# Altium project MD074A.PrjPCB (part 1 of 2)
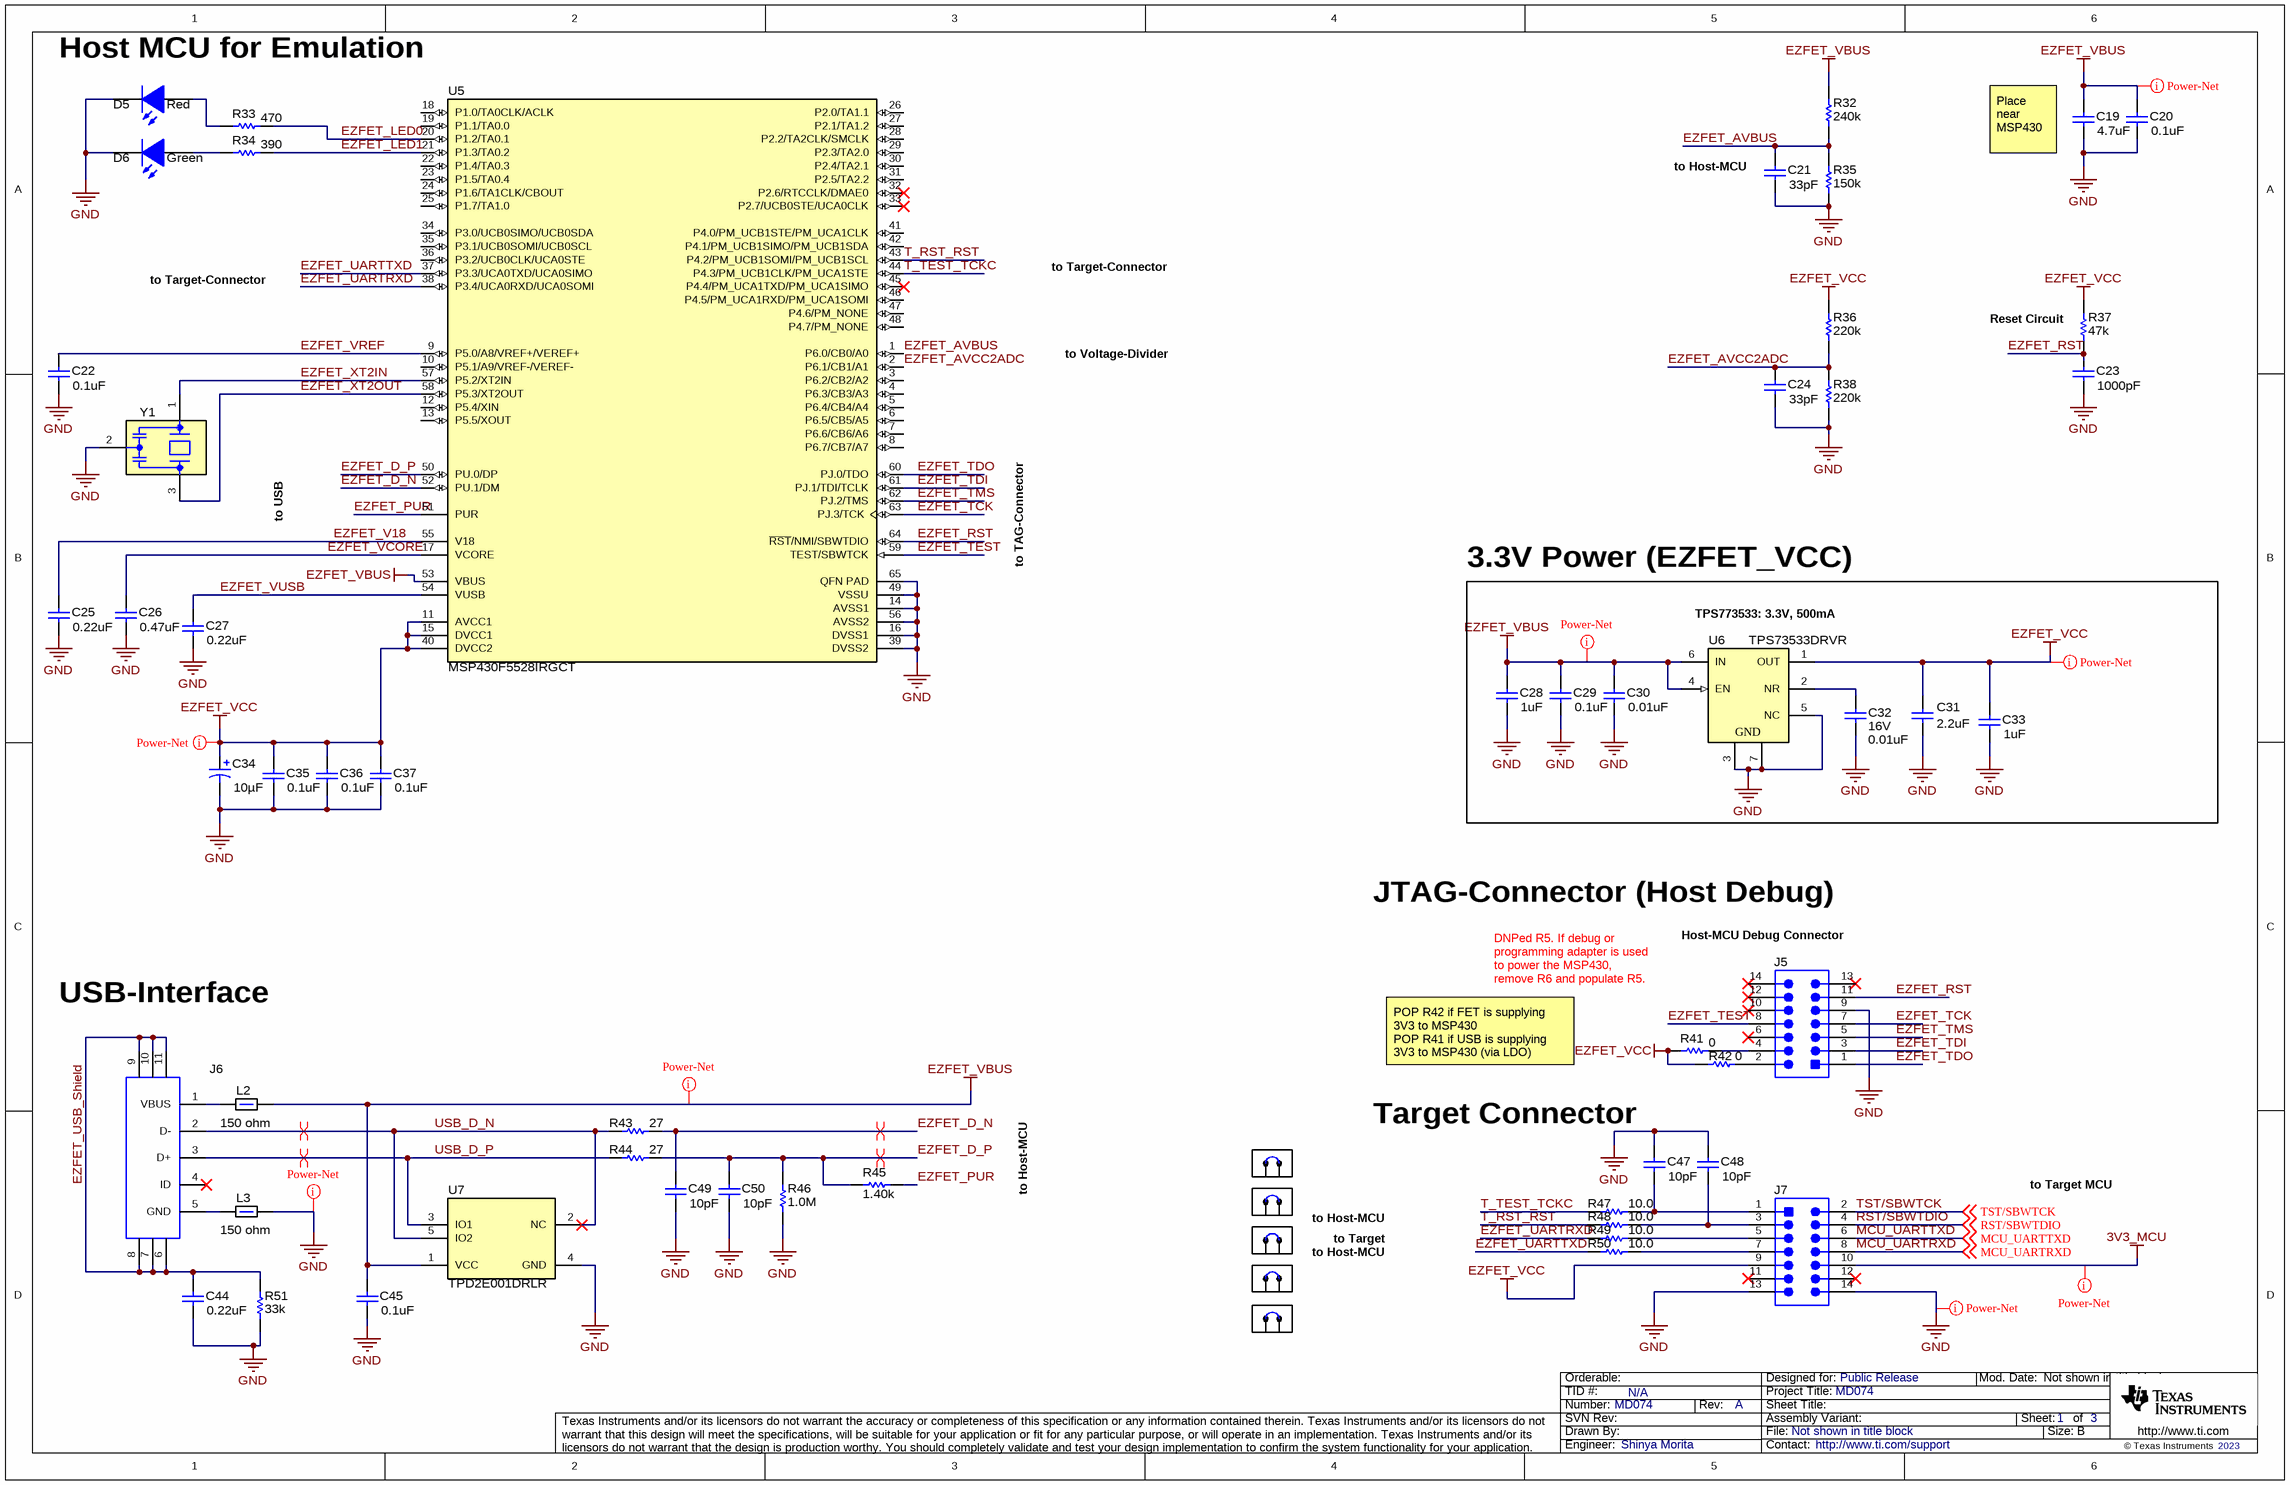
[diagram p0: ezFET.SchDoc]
CopyrightYear: 2023; PCB_Layout: Akshay Rajeev Menon; PCB_Rev: A; PRJ_Customer: Public Release; PRJ_Engineer: Shinya Morita; PRJ_Number: MD074; PRJ_Title: MD074; SCH_Rev: A; TechSupport: http://www.ti.com/support; TID: N/A
3 sheets, 218 parts. Net scope: global (net labels, ports and power ports of the same name join across sheets).
Board file: MD074A.PcbDoc
Sheets:
  ezFET.SchDoc
  MD074A_Hardware.SchDoc
  MD074A.SchDoc

## Sheet ezFET.SchDoc
size 431 x 279 mm; Date: Not shown in title block; ApprovedBy: Not shown in title block; CheckedBy: Not shown in title block; Author: Not shown in title block; CompanyName: Not shown in title block; Engineer: Not shown in title block; Organization: Not shown in title block; Address1: Not shown in title block; Address2: Not shown in title block; Address3: Not shown in title block; Address4: Not shown in title block; DocumentNumber: 1; Revision: Use project parameter SCH_Rev; SheetNumber: 1; SheetTotal: 3; PageSetup: Record=PageOptions¦CenterHorizontal=True¦CenterVertical=True¦PrintScale=1.00¦XCorrection=1.00¦YCorrection=1.00¦PrintKind=0¦BorderSize=5000000¦LeftOffset=0¦BottomOffset=0¦Orientation=2¦PaperLength=1000¦PaperWidth=1000¦Scale=100¦PaperSource=15¦PrintQuality=600¦MediaType=1¦DitherType=10¦PaperKind=Letter¦PrintScaleMode=1

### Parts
C19  ValueDisplayed: 4.7uF  [0402]  (hidden comment: C1005X5R1A475M050BC)
C20  ValueDisplayed: 0.1uF  [0402]  (hidden comment: GRM155R61A104KA01D)
C21  ValueDisplayed: 33pF  [0402]  (hidden comment: C1005C0G1H330J050BA)
C22  ValueDisplayed: 0.1uF  [0402]  (hidden comment: GRM155R61A104KA01D)
C23  ValueDisplayed: 1000pF  [0402]  (hidden comment: GRM155R71H102KA01D)
C24  ValueDisplayed: 33pF  [0402]  (hidden comment: C1005C0G1H330J050BA)
C25  ValueDisplayed: 0.22uF  [0402]  (hidden comment: GRM155R61A224KE19D)
C26  ValueDisplayed: 0.47uF  [0402]  (hidden comment: GRM155R61C474KE01)
C27  ValueDisplayed: 0.22uF  [0402]  (hidden comment: GRM155R61A224KE19D)
C28  ValueDisplayed: 1uF  [0402]  (hidden comment: 885012105012)
C29  ValueDisplayed: 0.1uF  [0402]  (hidden comment: GRM155R61A104KA01D)
C30  ValueDisplayed: 0.01uF  [0402]  (hidden comment: GRM155R71C103KA01D)
C31  2.2uF  [0402]
C32  VDC_V: 16V  ValueDisplayed: 0.01uF  [0402]  (hidden comment: GRM155R71C103KA01D)
C33  ValueDisplayed: 1uF  [0402]  (hidden comment: 885012105012)
C34  ValueDisplayed: 10µF  [3216-18]  (hidden comment: T520A106M010ATE080)
C35  ValueDisplayed: 0.1uF  [0402]  (hidden comment: GRM155R61A104KA01D)
C36  ValueDisplayed: 0.1uF  [0402]  (hidden comment: GRM155R61A104KA01D)
C37  ValueDisplayed: 0.1uF  [0402]  (hidden comment: GRM155R61A104KA01D)
C44  ValueDisplayed: 0.22uF  [0402]  (hidden comment: GRM155R61A224KE19D)
C45  ValueDisplayed: 0.1uF  [0402]  (hidden comment: GRM155R61A104KA01D)
C47  ValueDisplayed: 10pF  [0402]  (hidden comment: GRM1555C1H100FA01D)
C48  ValueDisplayed: 10pF  [0402]  (hidden comment: GRM1555C1H100FA01D)
C49  ValueDisplayed: 10pF  [0402S]  (hidden comment: GRM1555C1H100FA01D)
C50  ValueDisplayed: 10pF  [0402S]  (hidden comment: GRM1555C1H100FA01D)
D5  value Red  [WL-SMCW_RED]  (hidden comment: 150060RS75000)
D6  value Green  [WL-SMCW_GREEN]  (hidden comment: CMP-0002894-2)
J5  61301421121  [Wurth_61301421121]  (value not drawn)
J6  CMP-0055311-1  [Molex_1051640001]  (value not drawn)
J7  PEC07DAAN  [CONN_PEC07DAAN]  (value not drawn)
L2  value 150 ohm  [0603]  (hidden comment: BLM18AG151BH1D)
L3  ValueDisplayed: 150 ohm  [0603]  (hidden comment: BLM18AG151BH1D)
R32  ValueDisplayed: 240k  [0402]  (hidden comment: CRCW0402240KFKED)
R33  ValueDisplayed: 470  [0402]  (hidden comment: CRCW0402470RJNED)
R34  ValueDisplayed: 390  [0402]  (hidden comment: CRCW0402390RJNED)
R35  ValueDisplayed: 150k  [0402]  (hidden comment: CRCW0402150KFKED)
R36  ValueDisplayed: 220k  [0402]  (hidden comment: RC0402FR-07220KL)
R37  ValueDisplayed: 47k  [0402]  (hidden comment: CRCW040247K0JNED)
R38  ValueDisplayed: 220k  [0402]  (hidden comment: RC0402FR-07220KL)
R41  value 0  [0402L]  (hidden comment: ERJ-2GE0R00X)
R42  value 0  [0402L]  (hidden comment: ERJ-2GE0R00X)
R43  ValueDisplayed: 27  [0402]  (hidden comment: CRCW040227R0JNED)
R44  ValueDisplayed: 27  [0402]  (hidden comment: CRCW040227R0JNED)
R45  ValueDisplayed: 1.40k  [0402]  (hidden comment: CRCW04021K40FKED)
R46  ValueDisplayed: 1.0M  [0402]  (hidden comment: CRCW04021M00JNED)
R47  ValueDisplayed: 10.0  [0402]  (hidden comment: CRCW040210R0FKED)
R48  ValueDisplayed: 10.0  [0402]  (hidden comment: CRCW040210R0FKED)
R49  ValueDisplayed: 10.0  [0402]  (hidden comment: CRCW040210R0FKED)
R50  ValueDisplayed: 10.0  [0402]  (hidden comment: CRCW040210R0FKED)
R51  ValueDisplayed: 33k  [0402]  (hidden comment: CRCW040233K0JNED)
SH-J19  60900213421  [Wurth_60900213421]  (value not drawn)
SH-J20  60900213421  [Wurth_60900213421]  (value not drawn)
SH-J21  60900213421  [Wurth_60900213421]  (value not drawn)
SH-J22  60900213421  [Wurth_60900213421]  (value not drawn)
SH-J23  60900213421  [Wurth_60900213421]  (value not drawn)
U5  PartNumber: MSP430F5528IRGCT  [RGC0064B]  (hidden comment: CMP-0039269-4)
U6  TPS73533DRVR  [DRV0006A]
U7  TPD2E001DRLR  [DRL0005A]
Y1  CSTNR4M00GH5L000R0  [MuRata_CSTNR]  (value not drawn)

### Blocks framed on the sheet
3.3V Power (EZFET_VCC): C28-C33 U6

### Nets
3V3_MCU: J7.10
EZFET_VBUS: C19.1 C20.1 C28.1 C29.1 C30.1 C45.1 L2.2 R32.2 U5.53(VBUS) U6.4(EN) U6.6(IN) U7.1(VCC)
EZFET_VCC: C31.1 C33.1 C34.1(+) C35.1 C36.1 C37.1 J7.9 R36.2 R37.2 R41.1 R42.1 U5.11(AVCC1) U5.15(DVCC1) U5.40(DVCC2) U6.1(OUT)
GND: C19.2 C20.2 C21.2 C22.2 C23.2 C24.2 C25.2 C26.2 C27.2 C28.2 C29.2 C30.2 C31.2 C32.2 C33.2 C34.2(-) C35.2 C36.2 C37.2 C44.2 C45.2 C47.1 C48.1 C49.2 C50.2 D5.1(K) D6.1(K) J5.9 J7.13 J7.14 L3.2 R35.1 R38.1 R46.1 R51.1 U5.14(AVSS1) U5.16(DVSS1) U5.39(DVSS2) U5.49(VSSU) U5.56(AVSS2) U5.65(QFN_PAD) U6.3(GND) U6.5(NC) U6.7(GND) U7.4(GND) Y1.2(GND)
EZFET_AVBUS: C21.1 R32.1 R35.2 U5.1(P6.0/CB0/A0)
EZFET_AVCC2ADC: C24.1 R36.1 R38.2 U5.2(P6.1/CB1/A1)
EZFET_D_N: C49.1 R43.2 U5.52(PU.1/DM)
EZFET_D_P: C50.1 R44.2 R45.1 R46.2 U5.50(PU.0/DP)
EZFET_LED0: R33.2 U5.20(P1.2/TA0.1)
EZFET_LED1: R34.2 U5.21(P1.3/TA0.2)
EZFET_PUR: R45.2 U5.51(PUR)
EZFET_RST: C23.1 J5.11 R37.1 U5.64(~{RST}/NMI/SBWTDIO)
EZFET_TCK: J5.7 U5.63(PJ.3/TCK)
EZFET_TDI: J5.3 U5.61(PJ.1/TDI/TCLK)
EZFET_TDO: J5.1 U5.60(PJ.0/TDO)
EZFET_TEST: J5.8 U5.59(TEST/SBWTCK)
EZFET_TMS: J5.5 U5.62(PJ.2/TMS)
EZFET_UARTRXD: R49.1 U5.38(P3.4/UCA0RXD/UCA0SOMI)
EZFET_UARTTXD: R50.1 U5.37(P3.3/UCA0TXD/UCA0SIMO)
EZFET_USB_Shield: C44.1 J6.6 J6.7 J6.8 J6.9 J6.10 J6.11 R51.2
EZFET_V18: C25.1 U5.55(V18)
EZFET_VCORE: C26.1 U5.17(VCORE)
EZFET_VREF: C22.1 U5.9(P5.0/A8/VREF+/VEREF+)
EZFET_VUSB: C27.1 U5.54(VUSB)
EZFET_XT2IN: U5.57(P5.2/XT2IN) Y1.1(In)
EZFET_XT2OUT: U5.58(P5.3/XT2OUT) Y1.3(Out)
MCU_UARTRXD: J7.8 ; off-sheet MCU_UARTRXD
MCU_UARTTXD: J7.6 ; off-sheet MCU_UARTTXD
RST/SBWTDIO: J7.4 ; off-sheet RST/SBWTDIO
T_RST_RST: R48.1 U5.43(P4.2/PM_UCB1SOMI/PM_UCB1SCL)
T_TEST_TCKC: R47.1 U5.44(P4.3/PM_UCB1CLK/PM_UCA1STE)
TST/SBWTCK: J7.2 ; off-sheet TST/SBWTCK
USB_D_N: J6.2(D-) R43.1 U7.2(NC) U7.5(IO2)
USB_D_P: J6.3(D+) R44.1 U7.3(IO1)
NetC32_1: C32.1 U6.2(NR)
NetC47_2: C47.2 J7.1 R47.2
NetC48_2: C48.2 J7.3 R48.2
NetD5_2: D5.2(A) R33.1
NetD6_2: D6.2(A) R34.1
NetJ5_2: J5.2 R42.2
NetJ5_4: J5.4 R41.2
NetJ6_1: J6.1(VBUS) L2.1
NetJ6_5: J6.5(GND) L3.1
NetJ7_5: J7.5 R49.2
NetJ7_7: J7.7 R50.2

Not connected (* = marked no-connect by the designer): J5 6* 10* 12* 13* 14*; J6 4(ID)*; J7 11* 12*; U5 3(P6.2/CB2/A2) 4(P6.3/CB3/A3) 5(P6.4/CB4/A4) 6(P6.5/CB5/A5) 7(P6.6/CB6/A6) 8(P6.7/CB7/A7) 10(P5.1/A9/VREF-/VEREF-) 12(P5.4/XIN) 13(P5.5/XOUT) 18(P1.0/TA0CLK/ACLK) 19(P1.1/TA0.0) 22(P1.4/TA0.3) 23(P1.5/TA0.4) 24(P1.6/TA1CLK/CBOUT) 25(P1.7/TA1.0) 26(P2.0/TA1.1) 27(P2.1/TA1.2) 28(P2.2/TA2CLK/SMCLK) 29(P2.3/TA2.0) 30(P2.4/TA2.1) 31(P2.5/TA2.2) 32(P2.6/RTCCLK/DMAE0)* 33(P2.7/UCB0STE/UCA0CLK)* 34(P3.0/UCB0SIMO/UCB0SDA) 35(P3.1/UCB0SOMI/UCB0SCL) 36(P3.2/UCB0CLK/UCA0STE) 41(P4.0/PM_UCB1STE/PM_UCA1CLK) 42(P4.1/PM_UCB1SIMO/PM_UCB1SDA) 45(P4.4/PM_UCA1TXD/PM_UCA1SIMO)* 46(P4.5/PM_UCA1RXD/PM_UCA1SOMI) 47(P4.6/PM_NONE) 48(P4.7/PM_NONE)

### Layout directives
net class Power-Net: 3V3_MCU, EZFET_VBUS, EZFET_VCC, GND
differential pair: EZFET_D_N, EZFET_D_P, USB_D_N, USB_D_P

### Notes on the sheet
- (near D5) Host MCU for Emulation
- (near C21) to Host-MCU
- (near C19) Place near MSP430
- to Target-Connector
- to Voltage-Divider
- (near R37) Reset Circuit
- to USB
- to TAG-Connector
- (near U6) TPS773533: 3.3V, 500mA
- JTAG-Connector (Host Debug)
- (near J5) Host-MCU Debug Connector
- USB-Interface
- DNPed R5. If debug or programming adapter is used to power the MSP430, remove R6 and populate R5.
- POP R42 if FET is supplying 3V3 to MSP430
  POP R41 if USB is supplying 3V3 to MSP430 (via LDO)
- to Host-MCU
- Target Connector
- to Target
- to Target MCU

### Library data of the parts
C19 = CMP-0006269-2: CAP, CERM, 4.7 uF, 10 V, +/- 20%, X5R, 0402; Manufacturer: TDK; Alternate Manufacturer: Wurth Elektronik; Alternate PartNumber: 885012106012; TaMin_C: -55°C; Polarized: N; SizeAreaWB_mm2: 3; Value1: Unknown; U/M: EA; Value: 4.7uF; TaMax_C: 85°C; SizeZ_mm: 0.6; SizeX_mm: 1; SizeY_mm: 0.5; Value2: 10V; Cap_F: 4.7µF; AEC Category: Q200
C20 C22 C29 C35-C37 C45 = CMP-0006562-2: CAP, CERM, 0.1 uF, 10 V, +/- 10%, X5R, 0402; Manufacturer: MuRata; Alternate Manufacturer: Wurth Elektronik; Alternate PartNumber: 885012105010; TaMin_C: -55°C; Polarized: N; SizeAreaWB_mm2: 3; Value1: Unknown; U/M: EA; Value: 0.1uF; TaMax_C: 85°C; SizeZ_mm: 0.6; SizeX_mm: 1; SizeY_mm: 0.5; Value2: 10V; Cap_F: 100nF; AEC Category: Q200
C21 C24 = CMP-0006250-2: CAP, CERM, 33 pF, 50 V, +/- 5%, C0G/NP0, 0402; Manufacturer: TDK; Alternate Manufacturer: Wurth Elektronik; Alternate PartNumber: 885012005058; TaMin_C: -55°C; Polarized: N; SizeAreaWB_mm2: 3; Value1: Unknown; U/M: EA; Value: 33pF; TaMax_C: 125°C; SizeZ_mm: 0.6; SizeX_mm: 1; SizeY_mm: 0.5; Value2: 50V; AEC Category: Q200
C23 = CMP-0006673-2: CAP, CERM, 1000 pF, 50 V, +/- 10%, X7R, 0402; Manufacturer: MuRata; Alternate Manufacturer: Wurth Elektronik; Alternate PartNumber: 885012205061; TaMin_C: -55°C; Polarized: N; SizeAreaWB_mm2: 3; Value1: Unknown; U/M: EA; Value: 1000pF; TaMax_C: 125°C; SizeZ_mm: 0.6; SizeX_mm: 1; SizeY_mm: 0.5; Value2: 50V; Cap_F: 1nF; AEC Category: Q200
C25 C27 C44 = CMP-0006570-2: CAP, CERM, 0.22 uF, 10 V, +/- 10%, X5R, 0402; Manufacturer: MuRata; Alternate Manufacturer: Wurth Elektronik; Alternate PartNumber: 885012105011; TaMin_C: -55°C; Polarized: N; SizeAreaWB_mm2: 3; Value1: Unknown; U/M: EA; Value: 0.22uF; TaMax_C: 85°C; SizeZ_mm: 0.6; SizeX_mm: 1; SizeY_mm: 0.5; Value2: 10V; Cap_F: 220nF; AEC Category: Q200
C26 = CMP-0006600-2: CAP, CERM, 0.47 uF, 16 V, +/- 10%, X5R, 0402; Manufacturer: MuRata; TaMin_C: -55°C; Polarized: N; SizeAreaWB_mm2: 3; Value1: Unknown; U/M: EA; Value: 0.47uF; TaMax_C: 85°C; SizeZ_mm: 0.6; SizeX_mm: 1; SizeY_mm: 0.5; Value2: 16V; Cap_F: 470nF; AEC Category: Q200
C28 C33 = CMP-0064924-2: CAP, CERM, 1 uF, 10 V,+/- 20%, X5R, 0402; Manufacturer: Wurth Elektronik; TaMin_C: -55°C; Polarized: N; SizeAreaWB_mm2: 3; Value1: Unknown; U/M: EA; Value: 1uF; TaMax_C: 85°C; SizeZ_mm: 0.6; SizeX_mm: 1; SizeY_mm: 0.5; Value2: 10V; Cap_F: 1µF; AEC Category: Q200
C30 = CMP-0006639-2: CAP, CERM, 0.01 uF, 16 V, +/- 10%, X7R, 0402; Manufacturer: MuRata; Alternate Manufacturer: Wurth Elektronik; Alternate PartNumber: 885012205031; TaMin_C: -55°C; Polarized: N; SizeAreaWB_mm2: 3; Value1: Unknown; U/M: EA; Value: 0.01uF; TaMax_C: 125°C; SizeZ_mm: 0.6; SizeX_mm: 1; SizeY_mm: 0.5; Value2: 16V; Cap_F: 10nF; AEC Category: Q200
C31 = CMP-0006594-2: CAP, CERM, 2.2 uF, 16 V, +/- 10%, X5R, 0402; Manufacturer: MuRata; PartNumber: GRM155R61C225KE11D; TaMin_C: -55°C; Polarized: N; SizeAreaWB_mm2: 3; Value1: Unknown; U/M: EA; TaMax_C: 85°C; SizeZ_mm: 0.6; SizeX_mm: 1; SizeY_mm: 0.5; Value2: 16V; CompType: Capacitor; Cap_F: 2.2µF; AEC Category: Q200
C32 = CMP-0006639-2: CAP, CERM, 0.01 uF, 16 V, +/- 10%, X7R, 0402; Manufacturer: MuRata; TaMin_C: -55°C; Polarized: N; SizeAreaWB_mm2: 3; Value1: Unknown; U/M: EA; Value: 0.01uF; TaMax_C: 125°C; SizeZ_mm: 0.6; SizeX_mm: 1; SizeY_mm: 0.5; Cap_F: 10nF; AEC Category: Q200
C34 = CMP-0084376-1: CAP, Tantalum Polymer, 10 µF, 10 V,+/- 20%, 0.08 ohm, 3216-18 SMD; Manufacturer: Kemet; TaMin_C: -55°C; SizeArea_mm2: 5.12; Value: 10uF; SizeAreaWB_mm2: 10.92; SizeY_mm: 1.6; VDC_V: 10V; Polarized: Y; SizeX_mm: 3.2; AEC Qualified: N; TaMax_C: 105°C; SizeZ_mm: 1.8; ESR_ohm: 0.08; CompType: Capacitor; AEC Category: Q200
C47 C48 = CMP-0064916-2: CAP, CERM, 10 pF, 50 V,+/- 1%, C0G/NP0, 0402; Manufacturer: MuRata; Alternate Manufacturer: Wurth Elektronik; Alternate PartNumber: 885012005055; TaMin_C: -55°C; Polarized: N; SizeAreaWB_mm2: 3; Value1: Unknown; U/M: EA; Value: 10pF; TaMax_C: 125°C; SizeZ_mm: 0.6; SizeX_mm: 1; SizeY_mm: 0.5; Value2: 50V; AEC Category: Q200
C49 C50 = CMP-0064916-2: CAP, CERM, 10 pF, 50 V,+/- 1%, C0G/NP0, 0402; Manufacturer: MuRata; Alternate Manufacturer: Wurth Elektronik; Alternate PartNumber: 885012005055; TaMin_C: -55°C; Polarized: N; SizeAreaWB_mm2: 3; Value1: Unknown; U/M: EA; Value: 10pF; TaMax_C: 125°C; SizeZ_mm: 0.6; SizeX_mm: 1; SizeY_mm: 0.5; Cap_Case: 0402; Value2: 50V; AEC Category: Q200
D5 = CMP-0002947-3: LED, Red, SMD; Manufacturer: Wurth Elektronik; Type: AlInGaP; Vf_V: 2V; Io_A: 30mA; Vr_V: 5V; Tjmax_C: 85°C; Power_TotalModule: 72mW; Value1: 0.072W; Angle: 140
D6 = CMP-0002894-2: LED, Green, SMD; Manufacturer: Wurth Elektronik; PartNumber: 150060VS75000; Type: AlInGaP; Vf_V: 2V; Io_A: 20mA; Value1: W
J5 = CMP-0086014-1: Header, 2.54mm, 7x2, Gold, TH; Manufacturer: Wurth Elektronik; Pitch_mm: 2.54; Voltage_V: 250V; Shrouded: N; Gender: Male; Current_A: 3A; Cert_UL: Y; Row_Count: 2
J6 = CMP-0055311-1: Receptacle, USB 2.0, Micro B, 5 Position, R/A, SMT; PartNumber: 1051640001; Manufacturer: Molex; Pitch_mm: 0.65; Gender: Female; ContactFinish: Gold; Current_A: 1.8A; Voltage_V: 30V; Cert_UL: Y; CNHeader: FALSE; CT: TRUE
J7 = CMP-0002339-2: Header, 100mil, 7x2, Tin, TH; Manufacturer: Sullins Connector Solutions; Alternate Manufacturer: Wurth Elektronik; Alternate PartNumber: 61301421121; Current_A: 3A; Green_Lifecycle: Active; Shrouded: N; Gender: Male; Green_REACh: Passed; Voltage_V: 1.8kV; Row_Count: 2; RowSpacing_mm: 2.54; Cert_UL: Y
L2 = CMP-0081962-1: Ferrite Bead, 150 ohm @ 100 MHz, 0.7 A, 0603; Manufacturer: MuRata; SizeAreaWB_mm2: 4.68; SizeArea_mm2: 1.28; SizeZ_mm: 1; Imax_A: 700mA; ZTyp@100MHz_Ohm: 150; SizeY_mm: 0.8; Value2: 0.7A; Value1: 0.35 ohm; DCR_ohm: 0.35; SizeX_mm: 1.6
L3 = CMP-0081962-1: Ferrite Bead, 150 ohm @ 100 MHz, 0.7 A, 0603; Manufacturer: MuRata; SizeAreaWB_mm2: 4.68; SizeArea_mm2: 1.28; Value: 150 ohm; SizeZ_mm: 1; Imax_A: 700mA; ZTyp@100MHz_Ohm: 150; SizeY_mm: 0.8; Value2: 0.7A; Value1: 0.35 ohm; DCR_ohm: 0.35; SizeX_mm: 1.6
R32 = CMP-0026190-2: RES, 240 k, 1%, 0.063 W, AEC-Q200 Grade 0, 0402; Manufacturer: Vishay-Dale; Power_W: 63mW; TempCo: 100 ppm/C; Value: 240k; SizeX_mm: 1; SizeY_mm: 0.5; SizeZ_mm: 0.6; Value2: 0.063W; AEC Qualified: Y; VDC_V: 50V; AEC Category: Q200; AEC Grade: 0
R33 = CMP-0026934-3: RES, 470, 5%, 0.063 W, AEC-Q200 Grade 0, 0402; Manufacturer: Vishay-Dale; Value: 470; Value_Code: 470R; Power_W: 63mW; Value2: 0.063W; VDC_V: 50V; TempCo: 200 ppm/C; SizeArea_mm2: 0.5; SizeX_mm: 1; SizeZ_mm: 0.6; EIA_Code: E24; AEC Category: Q200; AEC Qualified: Y; AEC Grade: 0
R34 = CMP-0026914-3: RES, 390, 5%, 0.063 W, AEC-Q200 Grade 0, 0402; Manufacturer: Vishay-Dale; Value: 390; Value_Code: 390R; Power_W: 63mW; Value2: 0.063W; VDC_V: 50V; TempCo: 200 ppm/C; SizeArea_mm2: 0.5; SizeX_mm: 1; SizeZ_mm: 0.6; EIA_Code: E24; AEC Category: Q200; AEC Qualified: Y; AEC Grade: 0
R35 = CMP-0026021-3: RES, 150 k, 1%, 0.063 W, AEC-Q200 Grade 0, 0402; Manufacturer: Vishay-Dale; Power_W: 63mW; TempCo: 100 ppm/C; Value: 150k; EIA_Code: E96; SizeX_mm: 1; SizeY_mm: 0.5; SizeZ_mm: 0.6; Value2: 0.063W; AEC Qualified: Y; VDC_V: 50V; AEC Category: Q200; AEC Grade: 0
R36 R38 = CMP-0026728-1: RES, 220 k, 1%, 0.0625 W, 0402; Manufacturer: Yageo America; Power_W: 62.5mW; TempCo: 100 ppm/C; U/M: EA; Value: 220k; SizeX_mm: 1; SizeY_mm: 0.5; SizeZ_mm: 0.6; AEC Qualified: N; VDC_V: 50V; AEC Category: Q200
R37 = CMP-0026935-3: RES, 47 k, 5%, 0.063 W, AEC-Q200 Grade 0, 0402; Manufacturer: Vishay-Dale; Power_W: 63mW; TempCo: 200 ppm/C; Value_Code: 47k0; Value: 47k; EIA_Code: E24; SizeX_mm: 1; SizeY_mm: 0.5; SizeZ_mm: 0.6; Value2: 0.063W; AEC Qualified: Y; VDC_V: 50V; AEC Category: Q200; AEC Grade: 0
R41 R42 = CMP-0026992-3: RES, 0, 5%, 0.1 W, AEC-Q200 Grade 0, 0402; Manufacturer: Panasonic; Value_Code: 0000; Power_W: 100mW; Value2: 0.1W; VDC_V: 50V; TempCo: 600 ppm/C; EIA_Code: E24; AEC Category: Q200; AEC Qualified: Y; SizeArea_mm2: 0.5; SizeAreaWB_mm2: 3; SizeX_mm: 1; SizeZ_mm: 0.6
R43 R44 = CMP-0026888-3: RES, 27, 5%, 0.063 W, AEC-Q200 Grade 0, 0402; Manufacturer: Vishay-Dale; Power_W: 63mW; TempCo: 200 ppm/C; Value_Code: 27R0; Value: 27; EIA_Code: E24; SizeX_mm: 1; SizeY_mm: 0.5; SizeZ_mm: 0.6; Value2: 0.063W; AEC Qualified: Y; VDC_V: 50V; AEC Category: Q200; AEC Grade: 0
R45 = CMP-0026085-3: RES, 1.40 k, 1%, 0.063 W, AEC-Q200 Grade 0, 0402; Manufacturer: Vishay-Dale; Power_W: 63mW; TempCo: 100 ppm/C; Value_Code: 1k40; Value: 1.40k; EIA_Code: E96; Res_ohm: 1.4k; SizeX_mm: 1; SizeY_mm: 0.5; SizeZ_mm: 0.6; Value2: 0.063W; AEC Qualified: Y; VDC_V: 50V; AEC Category: Q200; AEC Grade: 0
R46 = CMP-0026859-2: RES, 1.0 M, 5%, 0.063 W, AEC-Q200 Grade 0, 0402; Manufacturer: Vishay-Dale; Power_W: 63mW; TempCo: 200 ppm/C; Value_Code: 1M00; Value: 1.0Meg; EIA_Code: E24; Res_ohm: 1M; SizeX_mm: 1; SizeY_mm: 0.5; SizeZ_mm: 0.6; Value2: 0.063W; AEC Qualified: Y; VDC_V: 50V; AEC Category: Q200; AEC Grade: 0
R47 = CMP-0025963-2: RES, 10.0, 1%, 0.063 W, 0402; Manufacturer: Vishay-Dale; Alternate Manufacturer: Wurth Elektronik; Alternate PartNumber: 560050310009; Power_W: 63mW; TempCo: 100 ppm/C; Value_Code: 10R0; U/M: EA; Value: 10.0; EIA_Code: E96; Res_ohm: 10; SizeX_mm: 1; SizeY_mm: 0.5; SizeZ_mm: 0.6; Value2: 0.063W; VDC_V: 50V; AEC Category: Q200
R48-R50 = CMP-0025963-2: RES, 10.0, 1%, 0.063 W, 0402; Manufacturer: Vishay-Dale; Power_W: 63mW; TempCo: 100 ppm/C; Value_Code: 10R0; U/M: EA; Value: 10.0; EIA_Code: E96; Res_ohm: 10; SizeX_mm: 1; SizeY_mm: 0.5; SizeZ_mm: 0.6; Value2: 0.063W; VDC_V: 50V; AEC Category: Q200
R51 = CMP-0026907-3: RES, 33 k, 5%, 0.063 W, AEC-Q200 Grade 0, 0402; Manufacturer: Vishay-Dale; Power_W: 63mW; TempCo: 200 ppm/C; Value_Code: 33k0; Value: 33k; EIA_Code: E24; SizeX_mm: 1; SizeY_mm: 0.5; SizeZ_mm: 0.6; Value2: 0.063W; AEC Qualified: Y; VDC_V: 50V; AEC Category: Q200; AEC Grade: 0
SH-J19-SH-J23 = CMP-0003761-2: Shunt, 2.54mm, Gold, Black; Manufacturer: Wurth Elektronik
U5 = CMP-0039269-4: 16-Bit Ultra-Low-Power Microcontroller, 128KB Flash, 8KB RAM, USB, 12Bit ADC, 2 USCIs, 32Bit HW MPY, RGC0064B (VQFN-64); Alternate Manufacturer: Texas Instruments; Alternate PartNumber: MSP430F5528IRGCR; ADC: 12-bit SAR; ADC Channels: 16; Brown Out Reset: Yes; DMA: 3; Flash(KB): 128; Frequency(MHz): 25; GPIO: 47; Multiplier: 32x32; SRAM(B): 8192; Timers - 16-bit: 4; USB: 1; USCI_A (UART/LIN/IrDA/SPI): 2; Rating: Catalog; SizeArea_mm2: 81.0; SizeZ_mm: 1.0; Green_REACh: Passed; AEC Qualified: N; AEC Category: Q200; CompType: IC; Green_Lifecycle: Active; SizeY_mm: 9.0; SizeAreaWB_mm2: 121.0
U6 = CMP-0036330-5: Single Output High PSRR LDO, 500 mA, Fixed 3.3 V Output, 2.7 to 6.5 V Input, with Low IQ, 6-pin SON (DRV), -40 to 125 degC, Green (RoHS & no Sb/Br); Manufacturer: Texas Instruments; SubFamily: Single Channel LDO; Vin(Max)(V): 6.5; Vin(Min)(V): 2.7; Iout(Max)(A): 0.5; Iq(Typ)(mA): 0.04; Fixed Output Options(V): 3.3; Vdo(Typ)(mV): 280; Accuracy(%): 2; CompType: IC; SizeAreaWB_mm2: 9; SizeArea_mm2: 4; SizeZ_mm: 0.8
U7 = CMP-0043096-2: Low-Capacitance + / - 15 kV ESD-Protection Array for High-Speed Data Interfaces, 2 Channels, -40 to +85 degC, 5-pin SOT (DRL), Green (RoHS & no Sb/Br); Manufacturer: Texas Instruments; IO Leakage Current(nA): 1; IO Capacitance(Typ)(pF): 1.5; USB High Speed: TRUE; SubFamily: ESD Solution; Breakdown Voltage(Min)(V): 11; IEC 61000-4-2 Air-Gap(+/- kV): 15; IEC 61000-4-2 Contact(+/- kV): 8
Y1 = CMP-0085483-1: Oscillator, 4 MHz, 700 ppm, 39 pF, SMD; Manufacturer: MuRata; SizeArea_mm2: 9; Load Capacitance: 39 pF; SizeZ_mm: 1.2; AEC Category: Q200; Frequency Tolerance: 700 ppm; SizeX_mm: 4.5; SizeAreaWB_mm2: 16.5; TaMax_C: 85°C; TaMin_C: -20°C; SizeY_mm: 2; AEC Qualified: N; Frequency_Fixed: 4MHz

## Sheet MD074A_Hardware.SchDoc
size 431 x 279 mm; Date: Not shown in title block; ApprovedBy: Not shown in title block; CheckedBy: Not shown in title block; Author: Not shown in title block; CompanyName: Not shown in title block; Engineer: Not shown in title block; Organization: Not shown in title block; Address1: Not shown in title block; Address2: Not shown in title block; Address3: Not shown in title block; Address4: Not shown in title block; DocumentNumber: 3; Revision: Use project parameter SCH_Rev; SheetNumber: 3; SheetTotal: 3; PageSetup: Record=PageOptions¦CenterHorizontal=True¦CenterVertical=True¦PrintScale=1.00¦XCorrection=1.00¦YCorrection=1.00¦PrintKind=0¦BorderSize=5000000¦LeftOffset=0¦BottomOffset=0¦Orientation=2¦PaperLength=1000¦PaperWidth=1000¦Scale=100¦PaperSource=15¦PrintQuality=600¦MediaType=1¦DitherType=10¦PaperKind=Letter¦PrintScaleMode=1
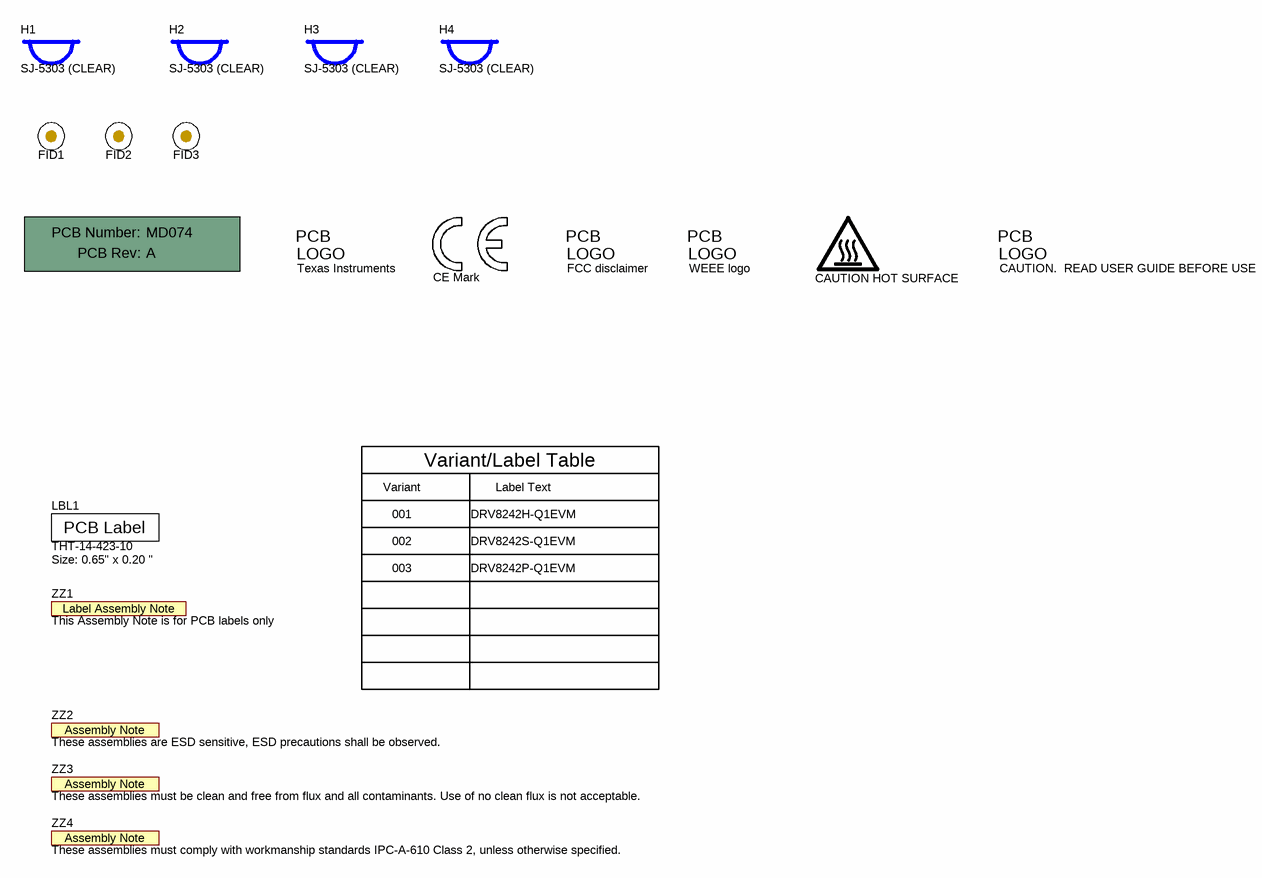
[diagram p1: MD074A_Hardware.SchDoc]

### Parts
!PCB1  Printed Circuit Board  (value not drawn)  (mechanical)
FID1  Fiducial  [Fiducial10-20]  (value not drawn)
FID2  Fiducial  [Fiducial10-20]  (value not drawn)
FID3  Fiducial  [Fiducial10-20]  (value not drawn)
H1  SJ-5303 (CLEAR)  [Bumpon_SJ5003Transparent]
H2  SJ-5303 (CLEAR)  [Bumpon_SJ5003Transparent]
H3  SJ-5303 (CLEAR)  [Bumpon_SJ5003Transparent]
H4  SJ-5303 (CLEAR)  [Bumpon_SJ5003Transparent]
LBL1  THT-14-423-10  Note: Size: 0.65" x 0.20 "  [Label_650x200]
Logo1  CE Mark  [CE_Mark_5mm]  (no BOM)
Logo2  Texas Instruments  [TI_Stacked_Overlay_Small]  (no BOM)
Logo3  FCC disclaimer  [FCC_disclaimer]  (no BOM)
Logo4  WEEE logo  [WEEE_Minimum]  (no BOM)
Logo5  CAUTION.  READ USER GUIDE BEFORE USE  [IEC_Caution_Small]  (no BOM)
LOGO6  CAUTION HOT SURFACE  [IEC_HotSurface_Small]  (no BOM)
ZZ1  This Assembly Note is for PCB labels only  [AssemblyNoteLabel]  (no BOM)
ZZ2  These assemblies are ESD sensitive, ESD precautions shall be observed.  [AssemblyNote]  (no BOM)
ZZ3  These assemblies must be clean and free from flux and all contaminants. Use of no clean flux is not acceptable.  [AssemblyNote]  (no BOM)
ZZ4  These assemblies must comply with workmanship standards IPC-A-610 Class 2, unless otherwise specified.  [AssemblyNote]  (no BOM)

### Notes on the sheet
- Variant
- Variant/Label Table
- Label Text
- 001
- 002
- DRV8242H-Q1EVM
- DRV8242S-Q1EVM
- 003
- DRV8242P-Q1EVM

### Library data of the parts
!PCB1 = CMP-0003618-2: Manufacturer: Any; PartNumber: MD074
FID1-FID3 = CMP-0077181-1: Fiducial mark.  There is nothing to buy or mount.
H1-H4 = CMP-0003620-1: Bumpon, Hemisphere, 0.44 X 0.20, Clear; Manufacturer: 3M
LBL1 = CMP-0003625-1: Thermal Transfer Printable Labels, 0.650" W x 0.200" H - 10,000 per roll; Manufacturer: Brady; CompType: Label
Logo1 = CMP-0074844-1: SymbolCreator: a0412235
Logo2 = CMP-0074838-1: Texas Instrument Corporate Signature; SymbolCreator: a0412235; Lib Reference: TI_Logo; Library Reference: Logo
Logo3 = CMP-0074847-1: FCC_disclaimer; Library Reference: Logo
Logo4 = CMP-0074769-1
Logo5 = CMP-0074836-1: IEC 61010-1 Caution Warning; SymbolCreator: a0412235; Lib Reference: IEC_Caution
LOGO6 = CMP-0074837-2: IEC 61010-1 Hot Surface Warning; Manufacturer: Texas Instruments; SymbolCreator: a0412235; CompType: IC; AEC Category: Q200
ZZ1 = CMP-0003616-3
ZZ2 = CMP-0077236-1
ZZ3 = CMP-0077237-1
ZZ4 = CMP-0077238-1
